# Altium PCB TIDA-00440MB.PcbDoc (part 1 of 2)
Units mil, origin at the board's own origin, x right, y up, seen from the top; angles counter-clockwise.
Board outline 4900 x 4330.71 mil, 4 copper layers (Top Layer, MidLayer1 (GND), MidLayer2 (PWR), Bottom Layer), stack 90 mil thick; 170 components, 89 nets, 419 pads, 132 vias.
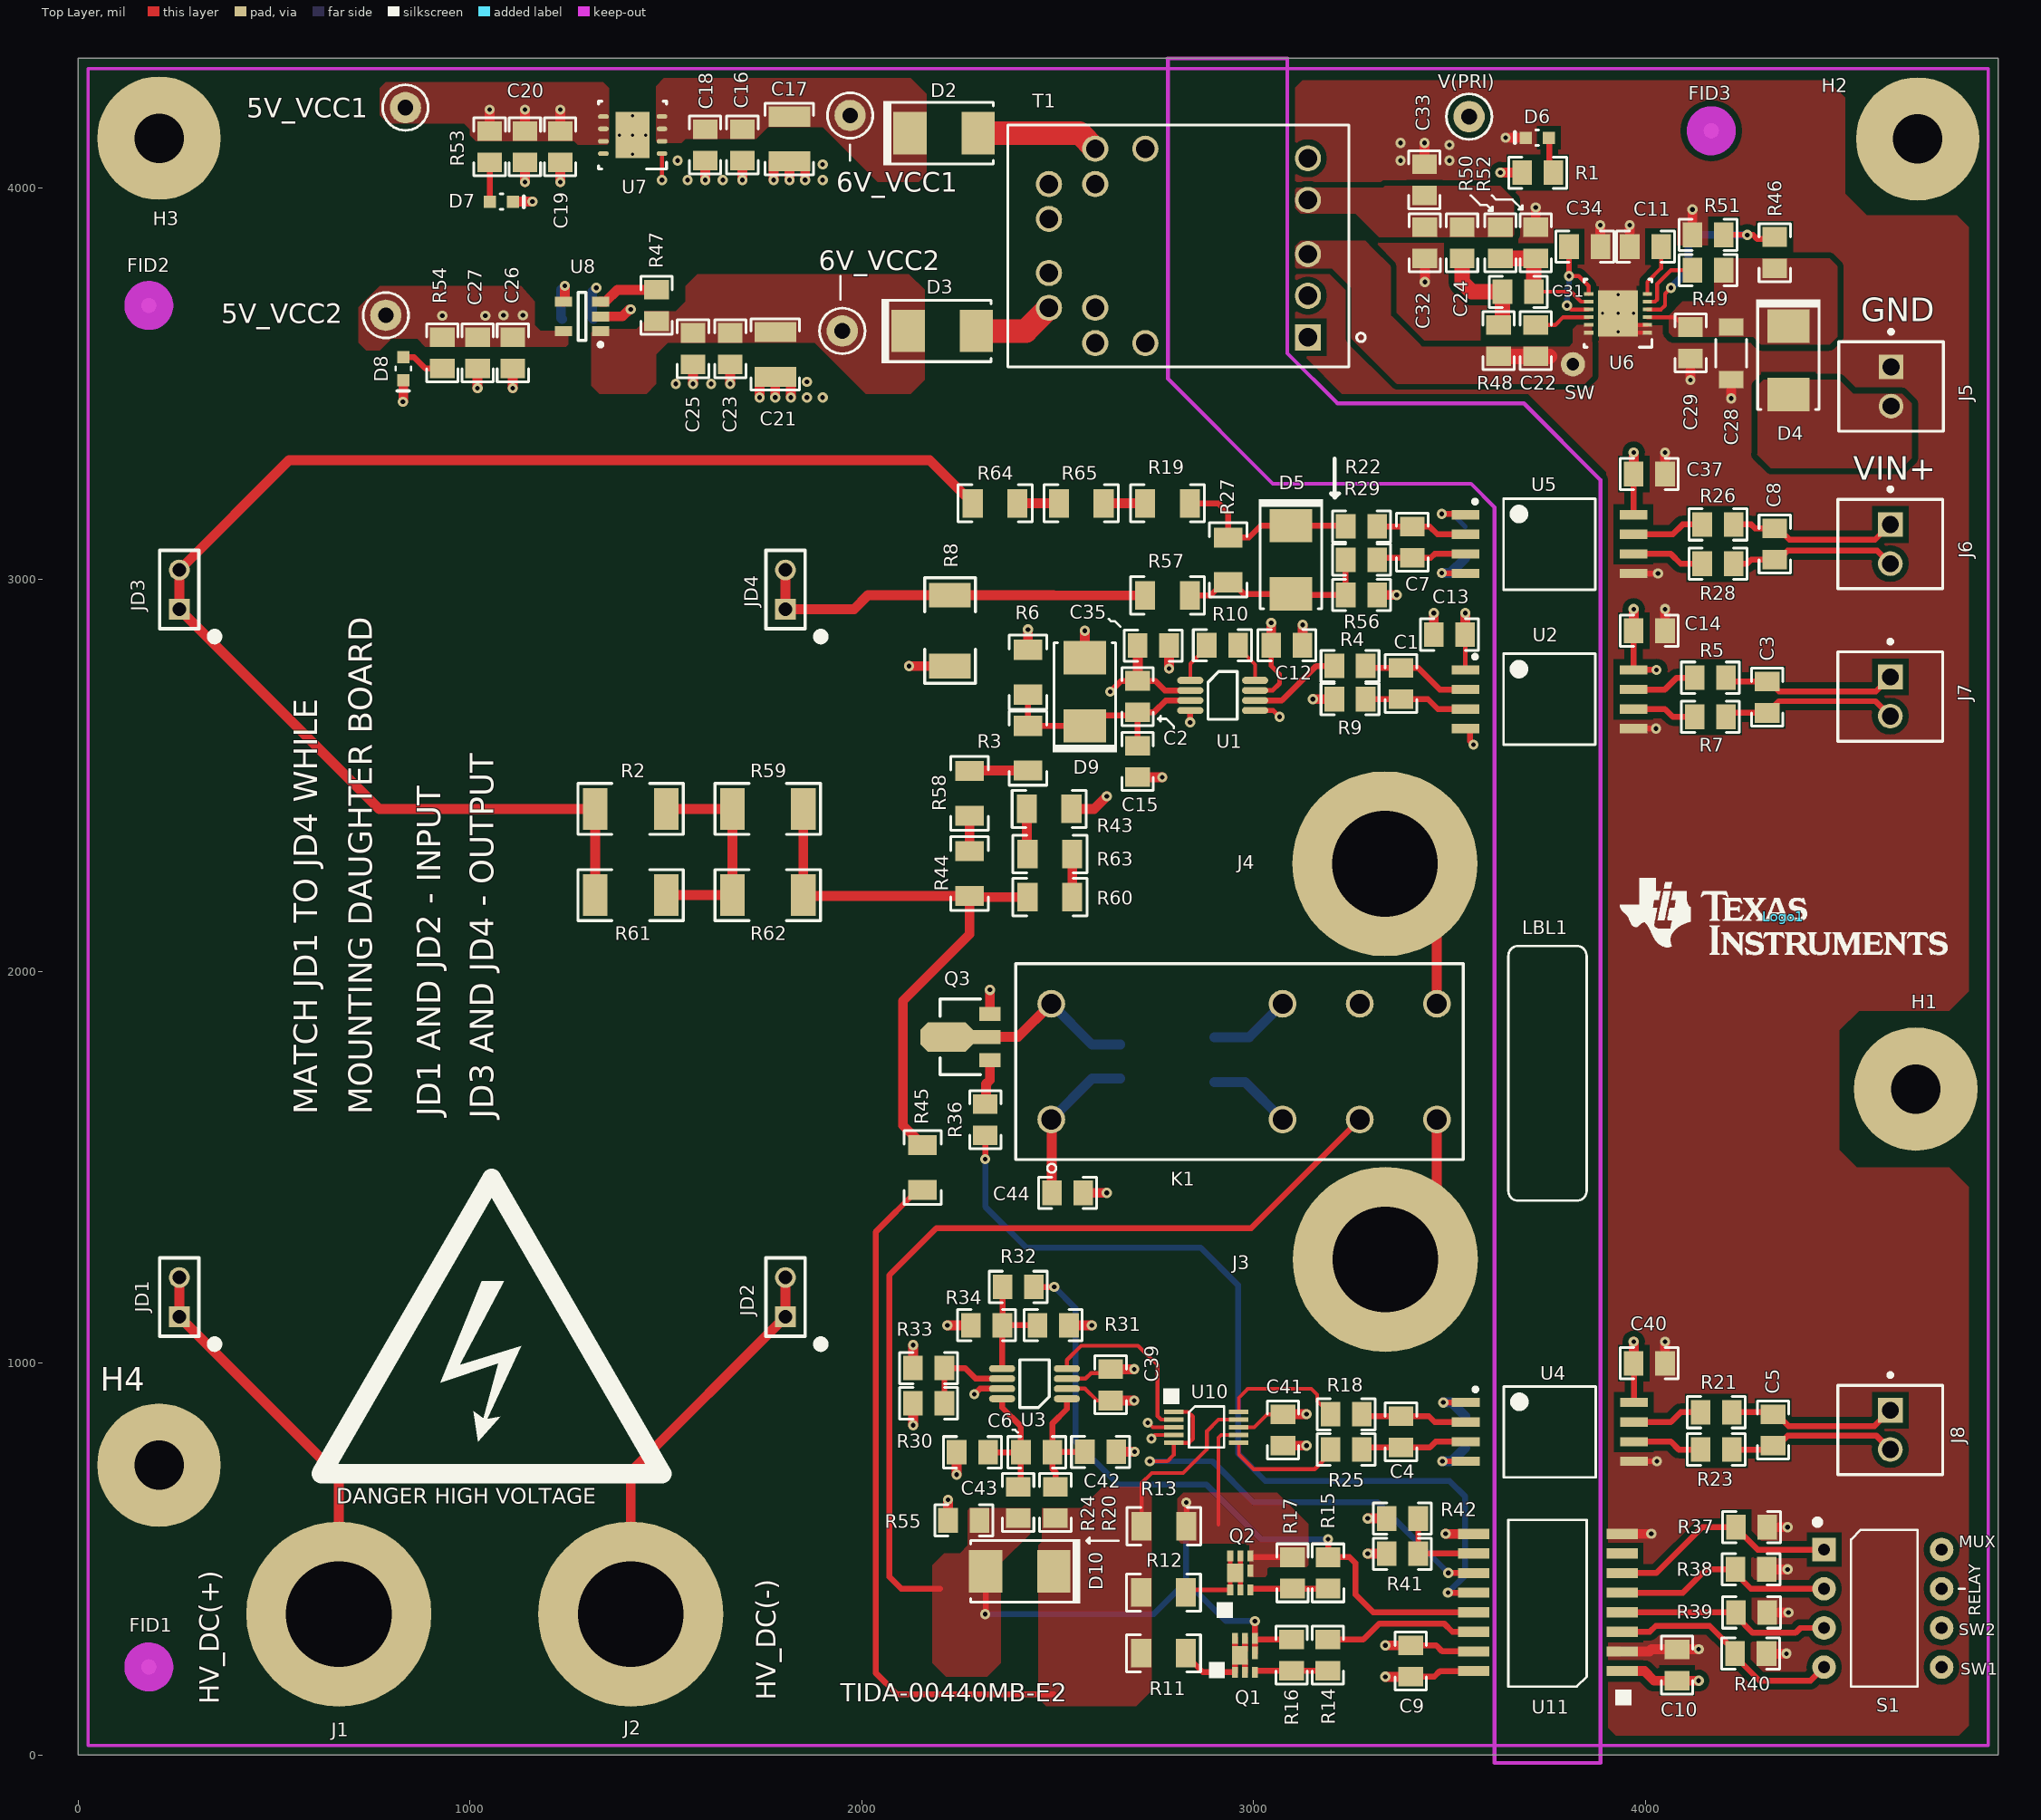
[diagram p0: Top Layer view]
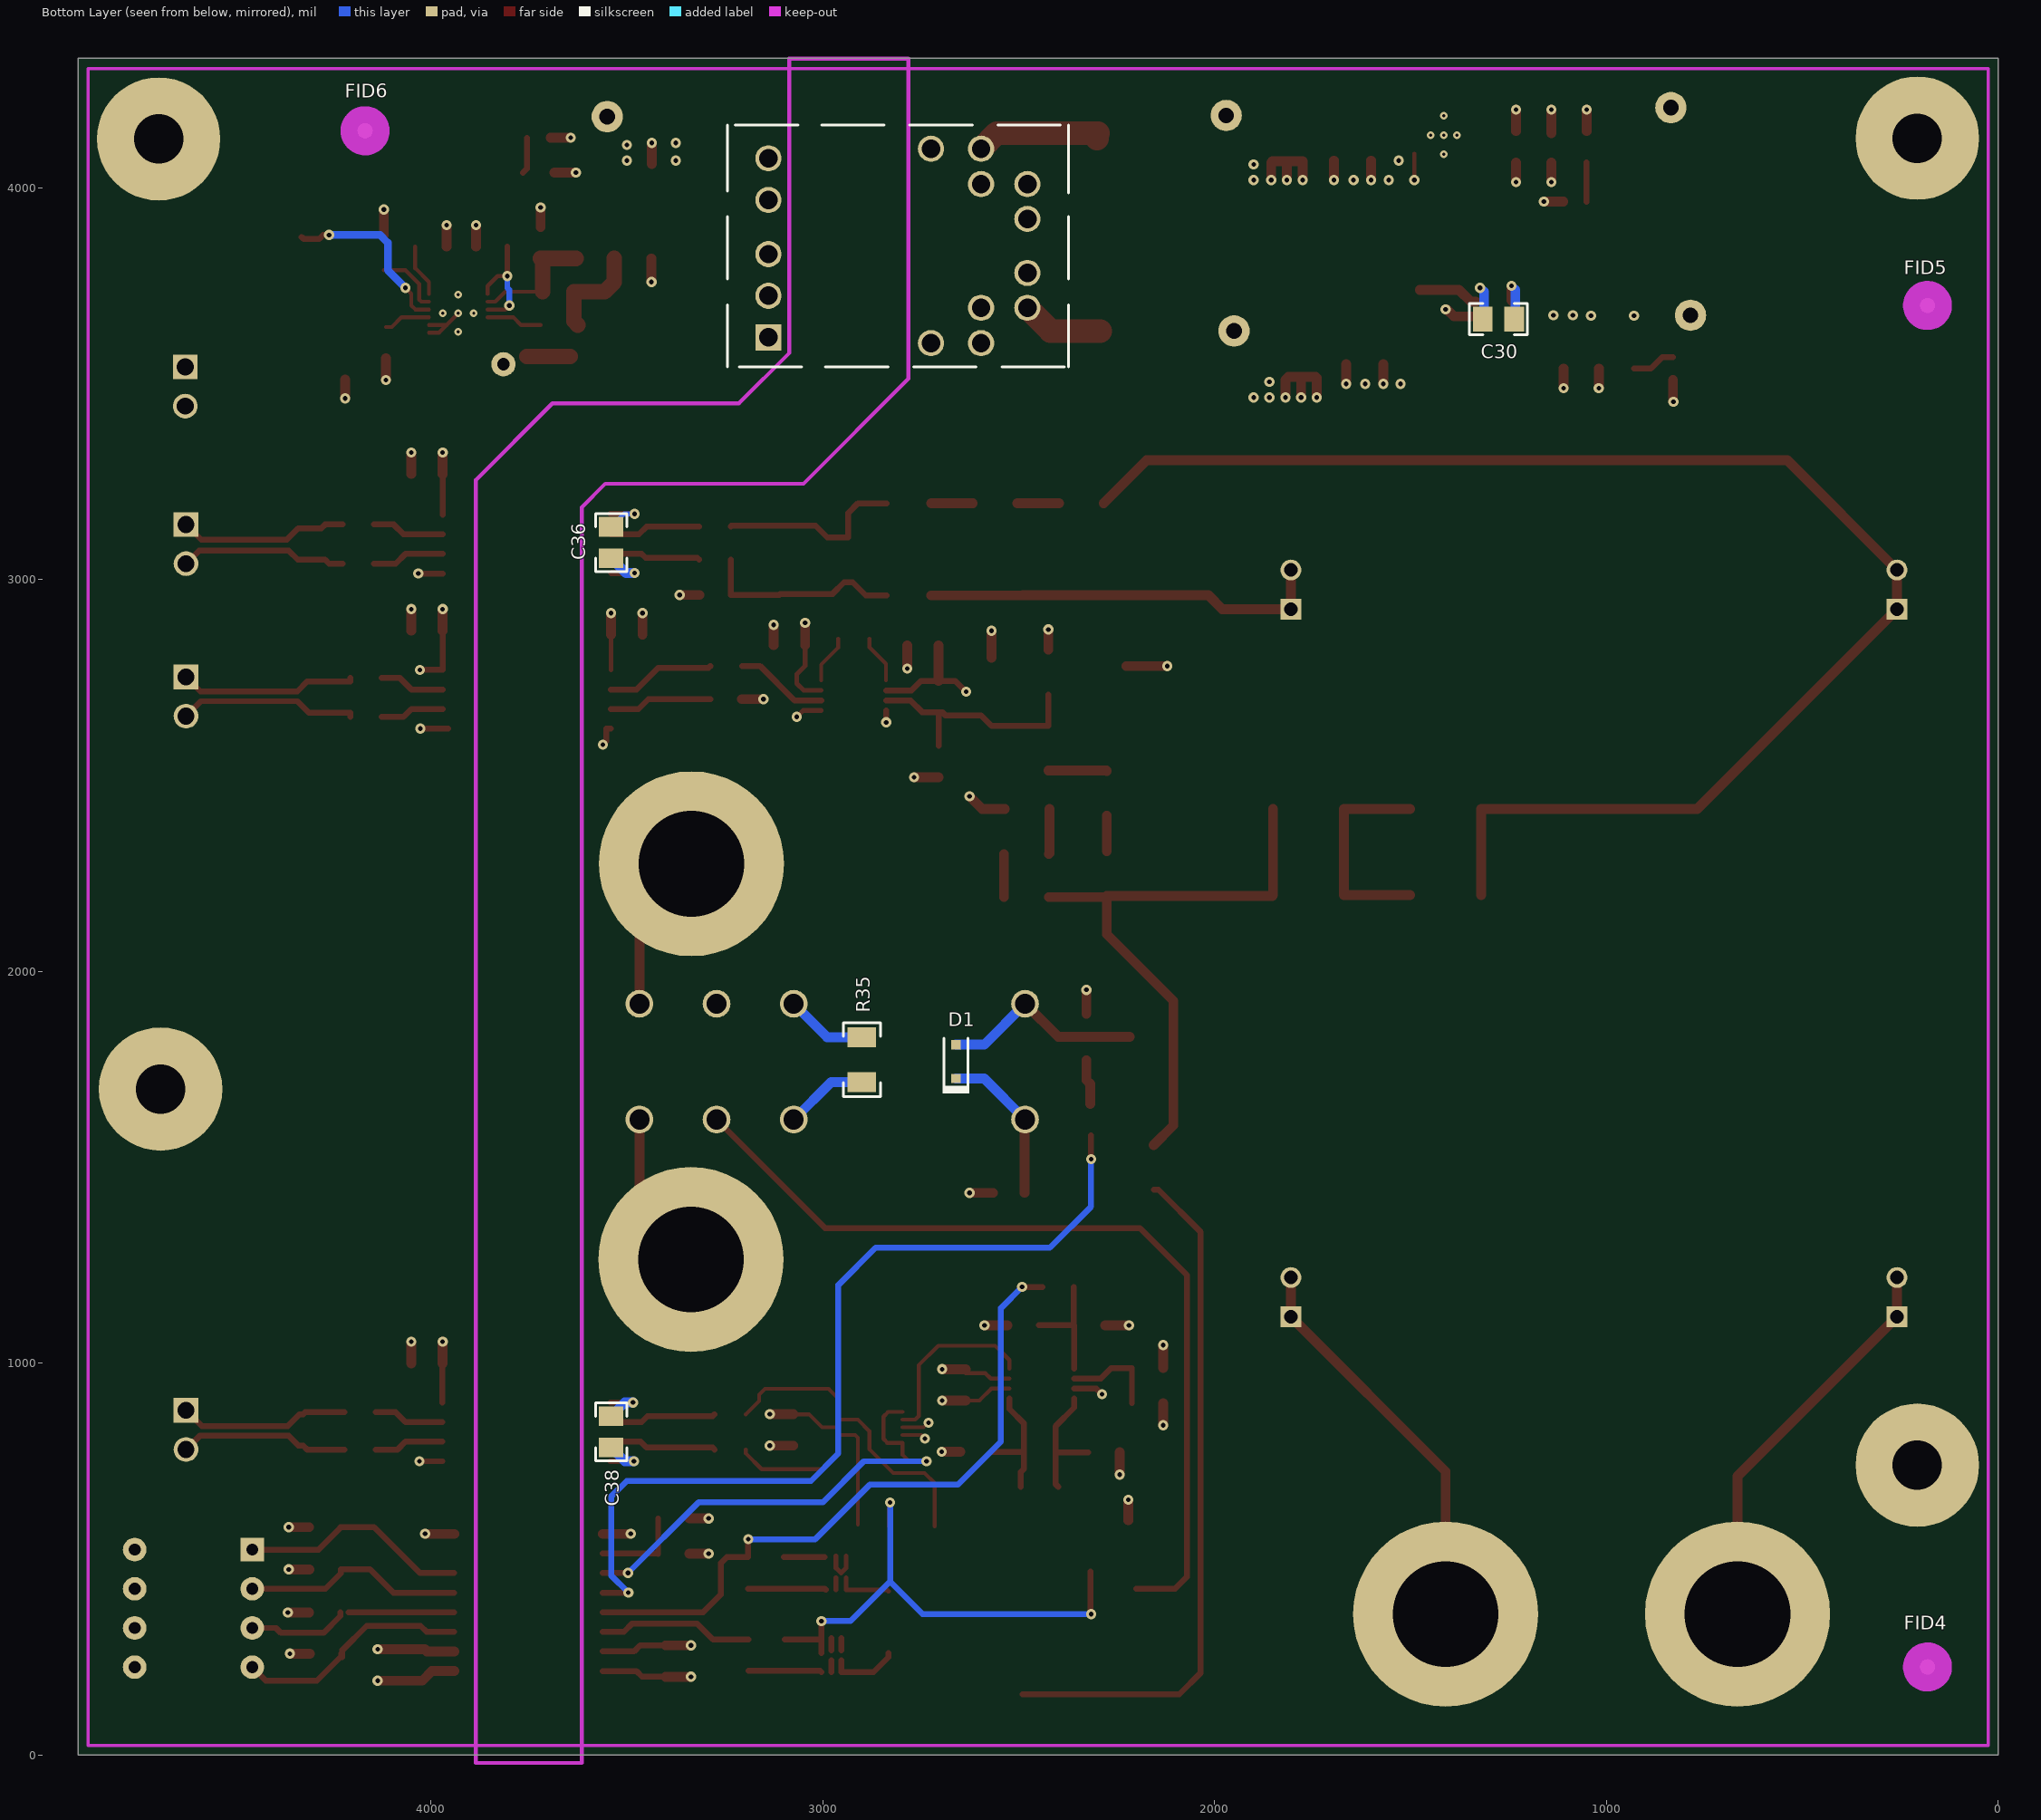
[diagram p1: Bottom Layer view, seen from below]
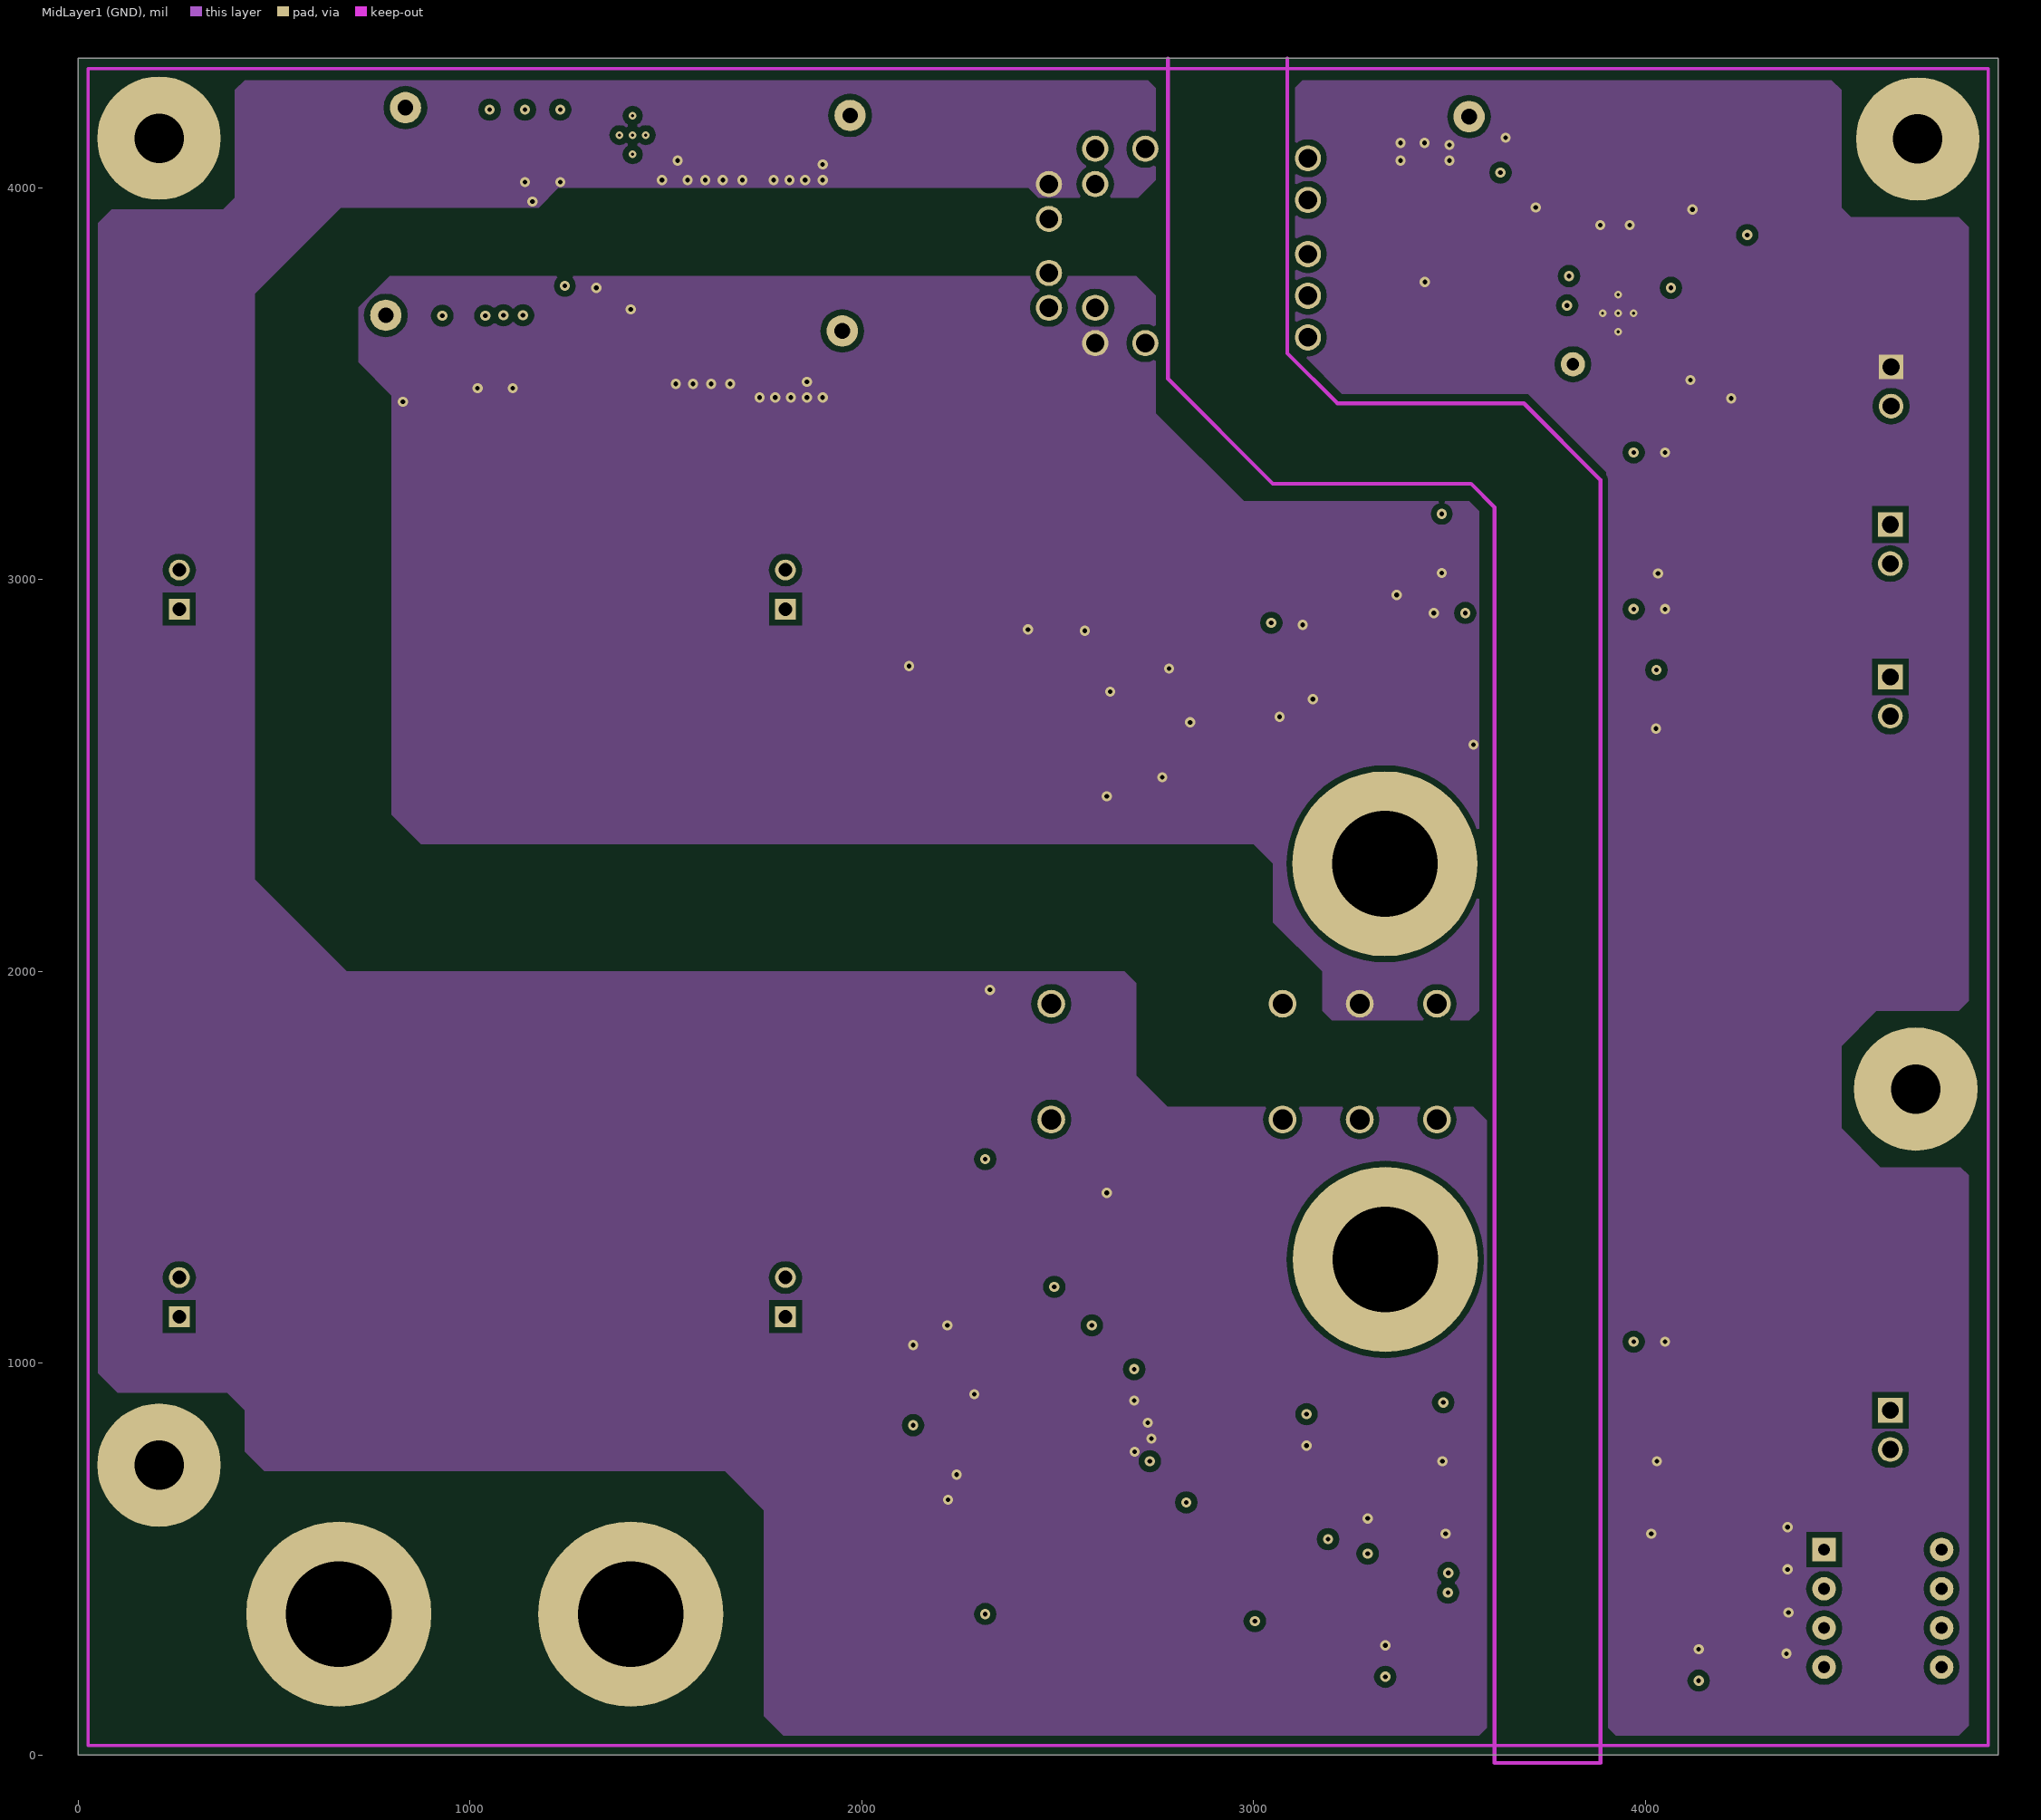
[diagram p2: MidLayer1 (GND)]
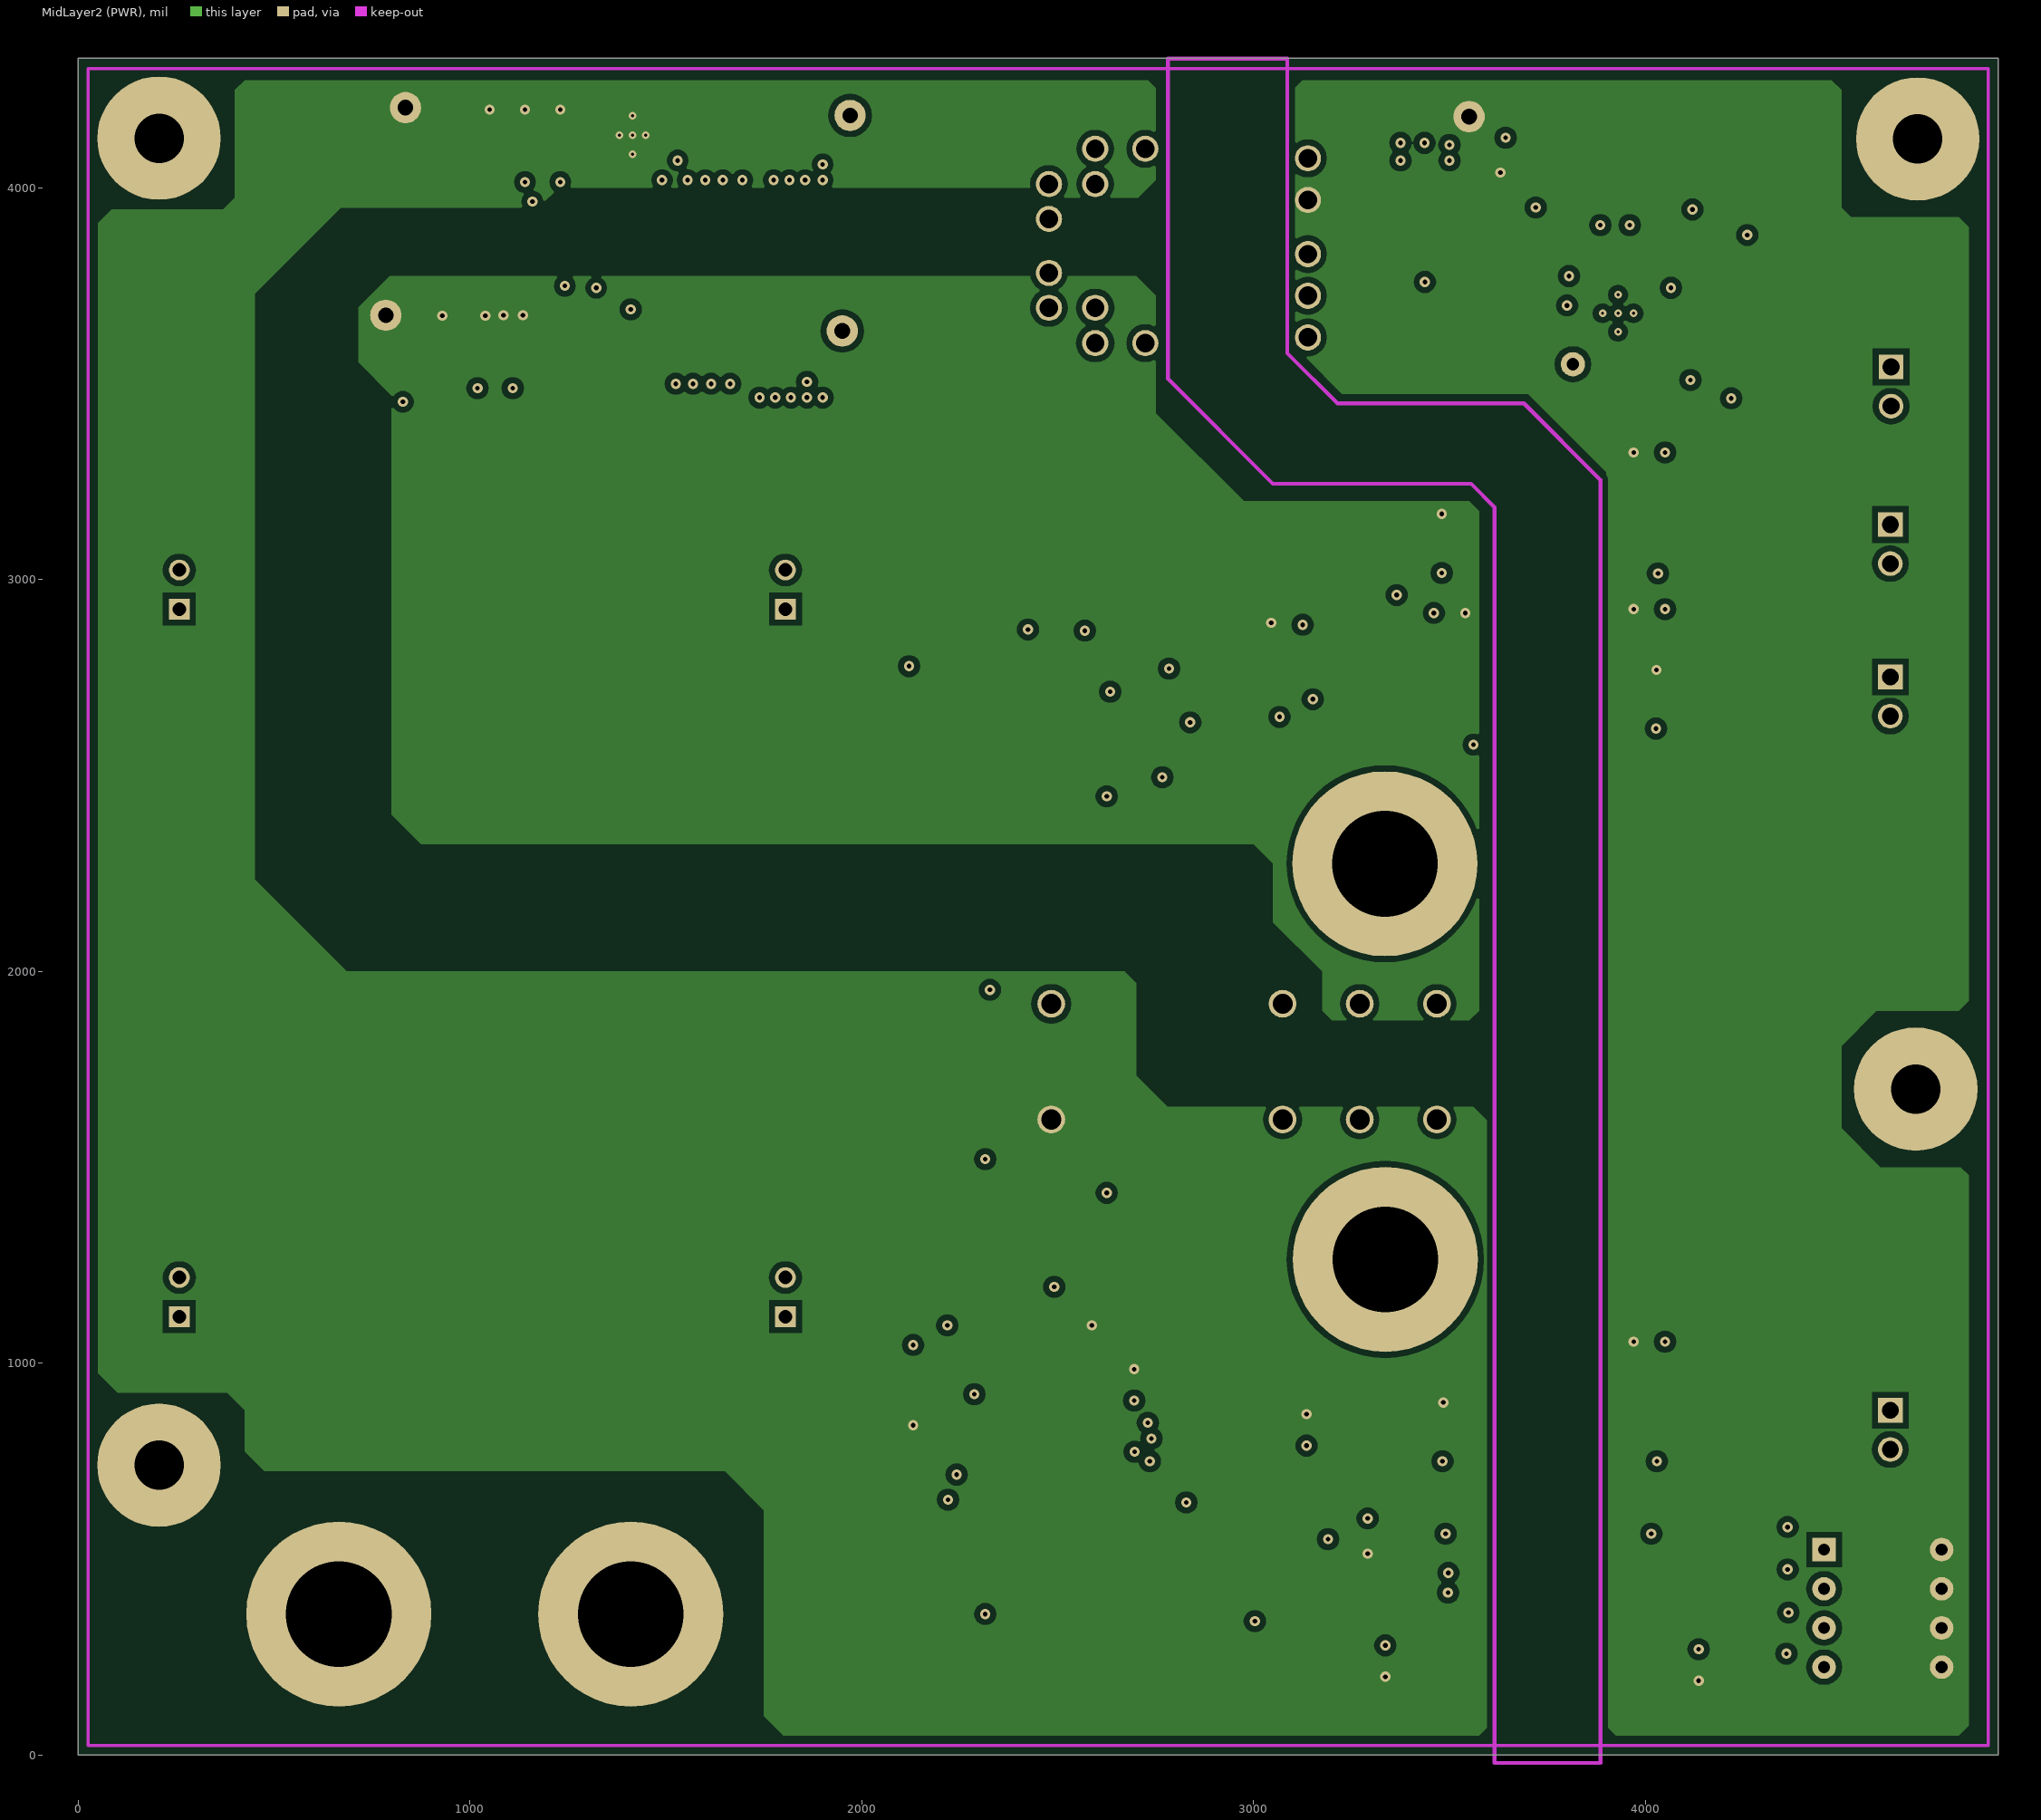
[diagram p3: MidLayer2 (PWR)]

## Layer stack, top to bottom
Top Layer: signal copper 1.4
Dielectric: core 59.2, FR-4, Dk 4.8
MidLayer1 (GND): signal copper 1.4
Dielectric: prepreg 12.6, FR-4, Dk 4.8
MidLayer2 (PWR): signal copper 1.4
Dielectric: core 12.6, FR-4, Dk 4.8
Bottom Layer: signal copper 1.4

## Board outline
0,0 0,4330.71 4900,4330.71 4900,0

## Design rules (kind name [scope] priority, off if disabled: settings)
AcuteAngle [All] p1: minimum=4.50000000000000E+0001 checktracksonly=FALSE
AssemblyTestPointUsage [All] p1: valid=2
Clearance "Poly_ All" [InPolygon] p1: gap=15
Clearance Poly_Poly [InPolygon vs InPolygon] p2: gap=15
Clearance "Less Than 9 mils from PAD to PAD" [(InPadClass('Less than 9 Mil Clearance')) vs (InPadClass('All Pads'))] p3: gap=8
Clearance "SMT Pin Via" [IsVia vs IsSMTPin] p4: gap=8
Clearance "Via to Via" [IsVia vs IsVia] p5: gap=8
Clearance [All] p6: gap=5
ComponentClearance ComponentClearance_Shunt [InComponentClass('Header') vs InComponentClass('Shunt')] p1: gap=0 collisioncheckmode=3 verticalgap=0 showdistances=FALSE
ComponentClearance ComponentClearance_Logo [InComponentClass('Logo')] p2: gap=50 collisioncheckmode=3 verticalgap=10 showdistances=FALSE
ComponentClearance ComponentClearance_ScrewToNut [(HasFootprint('NY PMS 440 0025 PH')) vs (HasFootprint('Keystone_1902C'))] p3: gap=5 collisioncheckmode=3 verticalgap=10 showdistances=FALSE
ComponentClearance ComponentClearance_MountingHoles [InComponentClass('Mounting Holes')] p4: gap=250 collisioncheckmode=3 verticalgap=100000 showdistances=FALSE
ComponentClearance ComponentClearance_SmallPassives [HasFootprint('0201*') or HasFootprint('0402*') or HasFootprint('0508') or HasFootprint('0603*') or HasFootprint('0612') or HasFootprint('0805*') or HasFootprint('0815*') or HasFootprint('0830*') or HasFootprint('1206*') or HasFootprint('1210*') or HasFootprint('1808*') or HasFootprint('1812*') or HasFootprint('1825*') or HasFootprint('2010*') or HasFootprint('2220*') or HasFootprint('2225*') or HasFootprint('2512*') or HasFootprint('2728*') or HasFootprint('3518*') vs HasFootprint('0201*') or HasFootprint('0402*') or HasFootprint('0508') or HasFootprint('0603*') or HasFootprint('0612') or HasFootprint('0805*') or HasFootprint('0815*') or HasFootprint('0830*') or HasFootprint('1206*') or HasFootprint('1210*') or HasFootprint('1808*') or HasFootprint('1812*') or HasFootprint('1825*') or HasFootprint('2010*') or HasFootprint('2220*') or HasFootprint('2225*') or HasFootprint('2512*') or HasFootprint('2728*') or HasFootprint('3518*')] p5: gap=20 collisioncheckmode=3 verticalgap=10 showdistances=FALSE
ComponentClearance ComponentClearance_THtoSMT [IsThruComponent vs IsSMTComponent] p6: gap=50 collisioncheckmode=3 verticalgap=30 showdistances=FALSE
ComponentClearance ComponentClearance_THtoTH [IsThruComponent vs IsThruComponent] p7: gap=118.11 collisioncheckmode=3 verticalgap=30 showdistances=FALSE
ComponentClearance [All] p8: gap=30 collisioncheckmode=3 verticalgap=10 showdistances=FALSE
DiffPairsRouting [All] p1: maxlimit=100 minlimit=10 mostfreqgap=10 maxuncoupledlength=1000
FabricationTestPointUsage TestPointUsage [All] p1: valid=2 allowmultiple=FALSE
FabricationTestpoint Testpoint [All] p1: side=3 testpointundercomponent=TRUE minsize=40 maxsize=100 preferedsize=60 minholesize=0 maxholesize=40 preferedholesize=32 testpointgrid=1 allowsidetop=TRUE allowsidebottom=TRUE usegrid=TRUE gridtolerance=0.01
FanoutControl Fanout_LCC [IsLCC] p1: bgadir=Out bgaviamode=Centered fanoutstyle=Auto fanoutdirection=Alternating viagrid=1 // Fanout_LCC (Default Rule)
FanoutControl Fanout_BGA [IsBGA] p2: bgadir=Out bgaviamode=Centered fanoutstyle=Auto fanoutdirection=Alternating viagrid=1 // Fanout_BGA (Default Rule)
FanoutControl Fanout_Default [All] p4: bgadir=Out bgaviamode=Centered fanoutstyle=Auto fanoutdirection=Alternating viagrid=1 // Fanout_Default (Default Rule)
FanoutControl Fanout_Small [(CompPinCount < 5)] p5: bgadir=Out bgaviamode=Centered fanoutstyle=Auto fanoutdirection=OutThenIn viagrid=1 // Fanout_Small (Default Rule)
HoleSize [All] p1: absolutevalues=TRUE maxlimit=300 minlimit=7 maxpercent=80.000 minpercent=20.000
MinimumAnnularRing MinimumAnnularRing_ThermalPadVias [IsVia and InAnyComponent] p1: minimumring=5.91
MinimumAnnularRing [All] p2: minimumring=5.91
MinimumSolderMaskSliver MinimumSolderMaskSliver_Logo [InComponentClass('Logo') vs InComponentClass('Logo')] p1: minsoldermaskwidth=0.7
MinimumSolderMaskSliver [All] p2: minsoldermaskwidth=3.94
PlaneConnect [All] p1: planeconnectstyle=Relief reliefexpansion=10 reliefentries=4 reliefconductorwidth=10 reliefairgap=10
PolygonConnect [All] p1: connectstyle=Direct reliefconductorwidth=10 reliefentries=4 polygonreliefangle="90 Angle" airgapwidth=10
RoutingVias [All] p1: holewidth=12 width=26 viastyle="Through Hole" minholewidth=12 minwidth=26 maxholewidth=20 maxwidth=40
SMDToCorner [All] p1: distance=30000
SilkToSilkClearance [All] p1: silktosilkclearance=0
SilkscreenOverComponentPads [All] p1: minsilkscreentomaskgap=5
SolderMaskExpansion [All] p1: expansion=2.5
Width PWR [InNetClass('PWR and GND')] p1: maxlimit=40 minlimit=10 preferedwidth=25 checkconnectedcopper=TRUE
Width [All] p2: maxlimit=100 minlimit=10 preferedwidth=15
14 further rules are at their usual default settings.

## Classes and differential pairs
component class FiducialMark: FID1 FID2 FID3 FID4 FID5 FID6
pad class "New Class": U7-9
component class "Mounting Holes": H1 H2 H3 H4
component class Logo: Logo1
pad class "Less than 9 Mil Clearance": U2-6 U2-7 U2-8
component class Pg2-Main: C1 C2 C3 C4 C5 C6 C7 C8 C9 C10 C12 C13 C14 C15 C35 C36 C37 C38 C39 C40 C41 C42 C43 C44 D1 D5 D9 D10 J1 J2 J3 J4 J6 J7 J8 JD1 JD2 JD3 JD4 K1 Q1 Q2 Q3 R2 R3 R4 R5 R6 R7 R8 R9 R10 R11 R12 R13 R14 R15 R16 R17 R18 R19 R20 R21 R22 R23 R24 R25 R26 R27 R28 R29 R30 R31 R32 R33 R34 R35 R36 R37 R38 R39 R40 R41 R42 R43 R44 R45 R55 R56 R57 R58 R59 R60 R61 R62 R63 R64 R65 S1 U1 U2 U3 U4 U5 U10 U11
component class AssemblyNote: ZZ1 ZZ2 ZZ3 ZZ4
component class Pg4_Hardware_ANSI-B: !PCB "DANGER HIGH VOLTAGE" FID1 FID2 FID3 FID4 FID5 FID6 H1 H2 H3 H4 LBL1 Logo1 ZZ1 ZZ2 ZZ3 ZZ4
component class Pg3: 5V_VCC1 5V_VCC2 6V_VCC1 6V_VCC2 C11 C16 C17 C18 C19 C20 C21 C22 C23 C24 C25 C26 C27 C28 C29 C30 C31 C32 C33 C34 D2 D3 D4 D6 D7 D8 J5 R1 R46 R47 R48 R49 R50 R51 R52 R53 R54 SW T1 U6 U7 U8 V(PRI)
component class Label: LBL1

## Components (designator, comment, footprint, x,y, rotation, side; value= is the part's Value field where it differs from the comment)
5V_VCC1 "5000" Keystone5000 835,4205 r180 top
5V_VCC2 "5000" Keystone5000 785,3675 r180 top
6V_VCC1 "5000" Keystone5000 1970,4185 r90 top
6V_VCC2 "5000" Keystone5000 1950,3635 r90 top
C1 "0805ZD105KAT2A" 0805_HV 3376,2735 r270 top
C2 "08055A101JAT2A" 0805_HV 2704,2702 r90 top
C3 "GRM216R71E102KA01D" 0805_HV 4311,2700 r270 top
C4 "0805ZD105KAT2A" 0805_HV 3376,825 r270 top
C5 "GRM216R71E102KA01D" 0805_HV 4326,830 r270 top
C6 "0805ZD105KAT2A" 0805_HV 2446,773 r180 top
C7 "0805ZD105KAT2A" 0805_HV 3405,3096 r270 top
C8 "GRM216R71E102KA01D" 0805_HV 4330,3091 r270 top
C9 "CC0805KRX7R7BB104" 0805_HV 3401,240 r90 top
C10 "CC0805KRX7R7BB104" 0805_HV 4081,230 r90 top
C11 "C2012C0G1E103J" 0805_HV 4000,3850 r180 top
C12 "CC0805KRX7R7BB104" 0805_HV 3085,2833 r0 top
C13 "CC0805KRX7R7BB104" 0805_HV 3500,2860 r180 top
C14 "CC0805KRX7R7BB104" 0805_HV 4010,2870 r0 top
C15 "C2012C0G1E103J" 0805_HV 2704,2536 r90 top
C16 "GRM21BR71A105KA01L" 0805_HV 1695,4110 r270 top
C17 "GRM32DR71A106KA01L" 1210 1815,4125 r270 top
C18 "CC0805KRX7R7BB104" 0805_HV 1600,4110 r270 top
C19 "CC0805KRX7R7BB104" 0805_HV 1230,4105 r270 top
C20 "GRM21BR71A105KA01L" 0805_HV 1140,4105 r270 top
C21 "GRM32DR71A106KA01L" 1210 1779,3575 r90 top
C22 "C2012C0G1E103J" 0805_HV 3720,3610 r270 top
C23 "GRM21BR71A105KA01L" 0805_HV 1664,3590 r270 top
C24 "C2012C0G1E103J" 0805_HV 3532,3860 r270 top
C25 "CC0805KRX7R7BB104" 0805_HV 1569,3590 r270 top
C26 "CC0805KRX7R7BB104" 0805_HV 1109,3579 r270 top
C27 "GRM21BR71A105KA01L" 0805_HV 1019,3579 r90 top
C28 "GMK316BJ106KL-T" 1206_190 4219,3578 r270 top
C29 "08053C104KAT2A" 0805_HV 4115,3605 r270 top
C30 "GRM216R71E102KA01D" 0805_HV 1275,3665 r0 bottom
C31 "GRM216R71E102KA01D" 0805_HV 3675,3735 r180 top
C32 "C2012JB1V226M125AC" 0805_HV 3437,3860 r270 top
C33 "C2012JB1V226M125AC" 0805_HV 3436,4021 r90 top
C34 "GMK212B7105KG-T" 0805_HV 3845,3850 r0 top
C35 "C2012C0G1E103J" 0805_HV 2744,2832 r0 top
C36 "CC0805KRX7R7BB104" 0805_HV 3540,3095 r270 bottom
C37 "CC0805KRX7R7BB104" 0805_HV 4010,3270 r0 top
C38 "CC0805KRX7R7BB104" 0805_HV 3540,825 r270 bottom
C39 "CC0805KRX7R7BB104" 0805_HV 2635,945 r270 top
C40 "CC0805KRX7R7BB104" 0805_HV 4010,1000 r0 top
C41 "CC0805KRX7R7BB104" 0805_HV 3075,830 r270 top
C42 "C2012C0G1E103J" 0805_HV 2609,774 r180 top
C43 "C2012C0G1E103J" 0805_HV 2282,773 r180 top
C44 "CC0805KRX7R7BB104" 0805_HV 2525,1435 r0 top
D1 "1SS315TPH3F" sod-323 2660,1770 r90 bottom
D2 "10BQ040TRPBF" SMB 2210,4140 r0 top
D3 "10BQ040TRPBF" SMB 2205,3635 r0 top
D4 "10BQ040TRPBF" SMB 4365,3560 r270 top
D5 "SMBJ5.0A-13-F" SMB 3095,3051 r270 top
D6 "LG L29K-G2J1-24-Z" "LG L29K_GREEN" 3724,4128 r180 top
D7 "LG L29K-G2J1-24-Z" "LG L29K_GREEN" 1080,3965 r0 top
D8 "LG L29K-G2J1-24-Z" "LG L29K_GREEN" 829.69,3538.94 r270 top
D9 "SMBJ5.0A-13-F" SMB 2569,2714 r90 top
D10 "SMBJ5.0A-13-F" SMB 2403,469 r180 top
"DANGER HIGH VOLTAGE" "DANGER HIGH VOLTAGE" IEC_HighVoltage_Large 1055,1070 r0 top
FID1 "Fiducial" Fiducial10-30 180,225 r0 top
FID2 "Fiducial" Fiducial10-30 180,3700 r90 top
FID3 "Fiducial" Fiducial10-30 4168,4146 r90 top
FID4 "Fiducial" Fiducial10-30 180,225 r90 bottom
FID5 "Fiducial" Fiducial10-30 180,3700 r90 bottom
FID6 "Fiducial" Fiducial10-30 4168,4146 r90 bottom
H1 "NY PMS 440 0025 PH" "NY PMS 440 0025 PH" 4690,1700 r0 top
H2 "NY PMS 440 0025 PH" "NY PMS 440 0025 PH" 4695,4125 r0 top
H3 "NY PMS 440 0025 PH" "NY PMS 440 0025 PH" 206,4127 r0 top
H4 "NY PMS 440 0025 PH" "NY PMS 440 0025 PH" 206,740 r0 top
J1 "3267" Pomona_3267 665,360 r90 top
J2 "3267" Pomona_3267 1410,360 r90 top
J3 "3267" Pomona_3267 3336,1265 r180 top
J4 "3267" Pomona_3267 3335,2275 r180 top
J5 "282834-2" TEC_282834-2 4627,3493 r270 top
J6 "282834-2" TEC_282834-2 4625,3091 r270 top
J7 "282834-2" TEC_282834-2 4625,2702 r270 top
J8 "282834-2" TEC_282834-2 4625,830 r270 top
JD1 "5-534206-1" CONN_534206-1 257.76,1169 r90 top
JD2 "5-534206-1" CONN_534206-1 1805,1169 r90 top
JD3 "5-534206-1" CONN_534206-1 257.76,2974.9 r90 top
JD4 "5-534206-1" CONN_534206-1 1805,2974.9 r90 top
K1 "G2RL-2 DC5" RELAY_G2RL-2_24 2946,1770 r0 top
LBL1 "Size: 0.65\" x 0.20 \"" Label_650x200 3750,1740 r90 top
Logo1 "Texas Instruments" TI_Stacked_Overlay_Small 4353,2140 r0 top
Q1 "TR-CSD13202Q2" SON_2X2MM 2977.8,255 r0 top
Q2 "TR-CSD13202Q2" SON_2X2MM 2966,465 r0 top
Q3 "2DD1664R-13" SOT-89-3 2252,1833 r180 top
R1 "CRCW08051K00FKEA" 0805_HV 3725,4039 r0 top
R2 "CRCW2010499KFKEF" 2010 1410,2415 r0 top
R3 "CRCW12067M50FKEA" 1206 2424,2570 r270 top
R4 "RT0805BRD0710RL" 0805_HV 3246,2780 r0 top
R5 "CRCW0805470RFKEA" 0805_HV 4166,2750 r0 top
R6 "CRCW12066K80JNEA" 1206 2424,2764 r270 top
R7 "CRCW0805470RFKEA" 0805_HV 4166,2650 r0 top
R8 "CRCW20100000Z0EF" 2010 2225,2870 r270 top
R9 "RT0805BRD0710RL" 0805_HV 3246,2695 r0 top
R10 "CRCW080551K0JNEA" 0805_HV 2920,2833 r0 top
R11 "RC1206FR-07261RL" 1206 2770,260 r180 top
R12 "RC1206FR-072K7L" 1206 2770,415 r180 top
R13 "RC1206FR-07220KL" 1206 2771,584 r180 top
R14 "CRCW08052K00FKEA" 0805_HV 3189.11,255 r270 top
R15 "CRCW08052K00FKEA" 0805_HV 3190,465 r270 top
R16 "CRCW080510K0FKEA" 0805_HV 3097.11,255 r270 top
R17 "CRCW080510K0FKEA" 0805_HV 3099,465 r270 top
R18 "RT0805BRD0710RL" 0805_HV 3236,870 r0 top
R19 "CRCW12063M00JNEA" 1206 2780,3195 r180 top
R20 "RT0805BRD0710RL" 0805_HV 2494,645 r90 top
R21 "CRCW0805470RFKEA" 0805_HV 4181,875 r0 top
R22 "RT0805BRD0710RL" 0805_HV 3275,3136 r0 top
R23 "CRCW0805470RFKEA" 0805_HV 4181,780 r0 top
R24 "RT0805BRD0710RL" 0805_HV 2399,645 r90 top
R25 "RT0805BRD0710RL" 0805_HV 3236,780 r0 top
R26 "CRCW0805470RFKEA" 0805_HV 4185,3141 r0 top
R27 "CRCW12063K00JNEA" 1206 2935,3050.69 r90 top
R28 "CRCW0805470RFKEA" 0805_HV 4185,3041 r0 top
R29 "RT0805BRD0710RL" 0805_HV 3275,3051 r0 top
R30 "ERJ-6GEY0R00V" 0805_HV 2170.69,898 r0 top
R31 "ERJ-6GEY0R00V" 0805_HV 2488.69,1097 r180 top
R32 "ERJ-6GEY0R00V" 0805_HV 2399,1195 r180 top
R33 "ERJ-6GEY0R00V" 0805_HV 2170.69,988 r0 top
R34 "ERJ-6GEY0R00V" 0805_HV 2318.69,1097 r0 top
R35 "CRCW120610M0JNEA" 1206 2900,1775 r270 bottom
R36 "ERJ-6GEY0R00V" 0805_HV 2315,1622 r270 top
R37 "ERJ-6GEY0R00V" 0805_HV 4271,582 r0 top
R38 "ERJ-6GEY0R00V" 0805_HV 4270,474 r0 top
R39 "ERJ-6GEY0R00V" 0805_HV 4271,364 r0 top
R40 "ERJ-6GEY0R00V" 0805_HV 4269,259 r0 top
R41 "ERJ-6GEY0R00V" 0805_HV 3380,514 r0 top
R42 "ERJ-6GEY0R00V" 0805_HV 3380,604 r0 top
R43 "CRCW12067M50FKEA" 1206 2478,2415 r180 top
R44 "CRCW12067M50FKEA" 1206 2275,2250 r270 top
R45 "CRCW12060000Z0EA" 1206 2155,1500 r90 top
R46 "RT0805BRD07126KL" 0805_HV 4330,3835 r270 top
R47 "ERJ-6GEY0R00V" 0805_HV 1476,3700 r270 top
R48 "RT0805BRD0735K2L" 0805_HV 3625,3610 r90 top
R49 "RT0805BRD07145KL" 0805_HV 4160,3790 r180 top
R50 "CRCW080512K7FKEA" 0805_HV 3630,3860 r90 top
R51 "CRCW080519K6FKEA" 0805_HV 4160,3880 r0 top
R52 "CRCW080520K0FKEA" 0805_HV 3720,3860 r270 top
R53 "CRCW08051K00FKEA" 0805_HV 1050,4105 r270 top
R54 "CRCW08051K00FKEA" 0805_HV 929,3579 r270 top
R55 "CRCW08050000Z0EA" 0805_HV 2260,599 r0 top
R56 "CRCW08050000Z0EA" 0805_HV 3275,2961 r180 top
R57 "CRCW12060000Z0EA" 1206 2780,2960 r0 top
R58 "CRCW12067M50FKEA" 1206 2275,2455 r270 top
R59 "CRCW2010499KFKEF" 2010 1760,2415 r0 top
R60 "CRCW12067M50FKEA" 1206 2480,2190 r180 top
R61 "CRCW2010499KFKEF" 2010 1410,2195 r0 top
R62 "CRCW2010499KFKEF" 2010 1760,2195 r0 top
R63 "CRCW12067M50FKEA" 1206 2480,2300 r0 top
R64 "CRCW12063M00JNEA" 1206 2340,3195 r180 top
R65 "CRCW12063M00JNEA" 1206 2560,3195 r180 top
S1 "78B04ST" SW_78B04ST 4606,374.53 r0 top
SW "TP-032_RND" TP-032_RND 3815,3550 r0 top
T1 "750342773" WURTH_750342773 2808,3852 r180 top
U1 "INA333AIDGK" DGK0008A_N 2921,2704.69 r0 top
U2 "AMC1200BDWV" DWV0008A 3755,2695 r0 top
U3 "INA225AIDGK" DGK0008A_N 2440.69,948 r180 top
U4 "AMC1200BDWV" DWV0008A 3756,825 r0 top
U5 "AMC1200BDWV" DWV0008A 3755,3091 r0 top
U6 "LM5160ADNTR" DNT0012B 3930,3680 r180 top
U7 "TLV1117-50IDRJR" DRJ0008A 1415,4135 r180 top
U8 "LP2985AIM5-5.0" MF05A_N 1285.68,3672 r180 top
U10 "TS5A23157DGS" DGS_10P 2878,837 r0 top
U11 "ISO7640FM" DW16 3751,389.53 r180 top
V(PRI) "5000" Keystone5000 3550,4182 r0 top
ZZ1 "This Assembly Note is for PCB labels only" AssemblyNoteLabel 180,4810 r0 top
ZZ2 "These assemblies are ESD sensitive, ESD precautions shall be observed." AssemblyNote 180,4740 r0 top
ZZ3 "These assemblies must be clean and free from flux and all contaminants. Use of no clean flux is not acceptable." AssemblyNote 180,4670 r0 top
ZZ4 "These assemblies must comply with workmanship standards IPC-A-610 Class 2, unless otherwise specified." AssemblyNote 180,4600 r0 top

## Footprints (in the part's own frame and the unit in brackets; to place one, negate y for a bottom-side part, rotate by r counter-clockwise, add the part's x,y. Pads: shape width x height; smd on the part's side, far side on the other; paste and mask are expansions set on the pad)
0805_HV [mil] "0805 with 30mil clearance between pads"
  rect 50x63 smd: 1(-40,0) 2(40,0)
  silkscreen extent -74,-40 74,40, body extent -43,-29 43,29, height 43
1206 [mm] "1206 from SM-752 data"
  rect 1.3x1.85 smd: 1(-1.45,0) 2(1.45,0)
  silkscreen extent -2.4,-1.21 2.4,1.21, body extent -1.7,-0.9 1.7,0.9, height 1.35
1206_190 [mm] "1206_190"
  rect 1.1x1.6 smd: 1(-1.7,0) 2(1.7,0)
  silkscreen extent -0.9,-1 0.9,1, body extent -1.75,-0.95 1.75,0.95, height 1.9
1210 [mm] "1210 from SM-752 data"
  rect 1.3x2.7 smd: 1(-1.45,0) 2(1.45,0)
  silkscreen extent -2.32,-1.57 2.32,1.57, body extent -1.7,-1.35 1.7,1.35, height 1.35
2010 [mm] "Chip Capacitor, Body 5.08x2.54mm, IPC Medium Density"
  rect 1.6x2.7 smd: 1(-2.3,0) 2(2.3,0)
  silkscreen extent -3.42,-1.65 3.42,1.65, body extent -2.73,-1.45 2.73,1.45, height 1.66
AssemblyNote [mil] "Assembly Note"
AssemblyNoteLabel [mil] "Assembly Note for PCB Labels"
CONN_534206-1 [mm] "TE_CONNECTIVITY"
  rect 1.35x1.35 hole 0.89: 1(-1.27,0)
  round 1.35 hole 0.89: 2(1.27,0)
  silkscreen extent -3.3,-2.54 2.54,1.27, body extent -2.51,-1.27 2.51,1.27, height 8.65
DGK0008A_N [mm] "TSOP, 8-Leads, Body 3x3mm, Pitch 0.65mm, IPC Medium Density"
  oval 1.7x0.45 smd mask+0.05: 1(-2.1,0.975) 2(-2.1,0.325) 3(-2.1,-0.325) 4(-2.1,-0.975) 5(2.1,-0.975) 6(2.1,-0.325) 7(2.1,0.325) 8(2.1,0.975)
  silkscreen extent -0.95,-1.55 0.95,1.55, body extent -2.45,-1.5 2.45,1.5, height 0.94
DGS_10P [mil]
  rect 50x11 smd: 1(-82,39) 2(-82,19.3) 3(-82,-0.4) 4(-82,-20.1) 5(-82,-39.8) 6(84,-39.8) 7(84,-20.1) 8(84,-0.4) 9(84,19.3) 10(84,39)
  silkscreen extent -108,59 -68,99
DNT0012B [mm] "SON, 12-Leads, Body 4x4mm, Pitch 0.5mm"
  rect 0.6x0.25 smd: 1(-1.9,1.25) 2(-1.9,0.75) 3(-1.9,0.25) 4(-1.9,-0.25) 5(-1.9,-0.75) 6(-1.9,-1.25) 7(1.9,-1.25) 8(1.9,-0.75) 9(1.9,-0.25) 10(1.9,0.25) 11(1.9,0.75) 12(1.9,1.25)
  rect 2.6x3 smd paste-1.3: 13(0,0)
  silkscreen extent -2.2,-2.2 2.2,2.2, body extent -2.05,-2.05 2.05,2.05, height 0.81
DRJ0008A [mm] "SON, 8-Leads, Body 4x4mm, Pitch 0.8mm, Thermal Pad 3x2.2mm, TI Recommended"
  oval 0.7x0.3 smd: 1(-1.9,1.2) 2(-1.9,0.4) 3(-1.9,-0.4) 4(-1.9,-1.2) 5(1.9,-1.2) 6(1.9,-0.4) 7(1.9,0.4) 8(1.9,1.2)
  rect 2.2x3 smd paste-1.1: 9(0,0)
  silkscreen extent -2.2,-2.2 2.2,2.2, body extent -2.05,-2.05 2.05,2.05, height 0.81
DW16 [mil]
  rect 80x26 smd: 1(-189.4,174.9) 2(-189.4,124.9) 3(-189.4,74.9) 4(-189.4,24.9) 5(-189.4,-25.1) 6(-189.4,-75.1) 7(-189.4,-125.1) 8(-189.4,-175.1) 9(189.6,-175.1) 10(189.6,-125.1) 11(189.6,-75.1) 12(189.6,-25.1) 13(189.6,24.9) 14(189.6,74.9) 15(189.6,124.9) 16(189.6,174.9)
  silkscreen extent -213,223 -173,263
DWV0008A [mm] "SOIC, 8-Leads, Body 5.95x7.6mm (max), Pitch 1.27mm"
  rect 1.8x0.6 smd: 1(-5.45,1.905) 2(-5.45,0.635) 3(-5.45,-0.635) 4(-5.45,-1.905) 5(5.45,-1.905) 6(5.45,-0.635) 7(5.45,0.635) 8(5.45,1.905)
  silkscreen extent -4.95,-2.95 2.98,2.95, body extent -3.8,-2.98 3.8,2.98, height 2.81
Fiducial10-30 [mm]
  round 1 smd mask+1: 1(0,0)
  Top Layer keep-out circle w1.678: c0,0 r0.75
IEC_HighVoltage_Large [mil]
  silkscreen extent -435,-352 435,401
Keystone5000 [mil] "For Keystone 500x miniature loop terminals"
  round 80 hole 40: 1(0,0)
  silkscreen extent -58,-58 58,58, body extent -49,-49 49,49, height 182
Label_650x200 [mil] "Thermal Transfer Label"
  round 1 on Mech13: 0(0,0)
  silkscreen extent -325,-100 325,100, body extent -326,-101 326,101, height 1
"LG L29K_GREEN" [mm] "OSRAM"
  rect 0.8x0.8 smd paste-0.4: 1(-0.75,0) 2(0.75,0)
  silkscreen extent -0.1,-0.5 1.45,0.5, body extent -0.9,-0.45 0.9,0.45, height 0.67
MF05A_N [mm] "SOT23, 5-Leads, Body 2.9x1.6mm, Pitch 0.95mm, Lead Span 2.8mm, IPC Medium Density"
  rect 1.1x0.65 smd: 1(-1.2,0.95) 2(-1.2,0) 3(-1.2,-0.95) 4(1.2,-0.95) 5(1.2,0.95)
  silkscreen extent -1.33,-1.55 0.25,1.95, body extent -0.9,-1.55 0.9,1.55, height 1.19
"NY PMS 440 0025 PH" [mm] "4-40 nylon screw and mounting hole"
  round 8 hole 3.2: 1(0,0)
  body extent -3.3,-3.3 3.3,3.3, height 2.69
Pomona_3267 [mm] "Standard Uninsulated Banana Jack"
  round 12 hole 6.858: 1(0,0)
  body extent -4.12,-4.82 4.26,4.85, height 2.79
RELAY_G2RL-2_24 [mm] "OMRON"
  round 1.8 hole 1.3: 1(-11.75,-3.75) 2(3.25,-3.75) 3(8.25,-3.75) 4(13.25,-3.75) 5(13.25,3.75) 6(8.25,3.75) 7(3.25,3.75) 8(-11.75,3.75)
  silkscreen extent -14.05,-6.35 14.95,6.35, body extent -14.05,-6.36 14.95,6.36, height 15.7
SMB [mil] "Molded Diode, 2-Leads, Body 5.4x3.6mm, IPC Medium Density, based on OnSemi component dimensions"
  rect 85x107.99 smd: 1(-87.01,0) 2(87.01,0)
  silkscreen extent -155,-82 125,82, body extent -106,-71 106,71, height 91
sod-323 [mm] "NXP recommended land pattern"
  rect 0.6x0.6 smd paste-0.05: 1(-1.1,0) 2(1.1,0)
  silkscreen extent -2.06,-0.86 1.53,0.86, body extent -1.3,-0.67 1.3,0.68, height 1.1
SON_2X2MM [mm]
  rect 0.4x0.7 smd mask+0.05: 1(-0.65,-1.1) 2(0,-1.1) 3(0.65,-1.1) 4(0.65,1.1) 5(0,1.1) 6(-0.65,1.1)
  rect 1.05x1.2 smd mask+0.05: 7(-0.325,0)
  rect 0.4x0.8 smd mask+0.05: 8(0.65,0.15)
  silkscreen extent -2.33,-1.47 -1.32,-0.46
SOT-89-3 [mm] "SOT, 3-Leads, Body 4.6 x 2.6 mm, Pitch 1.5mm"
  rect 1.4x0.9 smd: 1(-1.9,1.5) 3(-1.9,-1.5)
  rect 1.8x0.9 smd: 2(-1.7,0)
  oct 3.4x1.9 smd: 4(0.9,0)
  silkscreen extent -1.3,-2.45 1.33,2.45, body extent -2.42,-2.28 1.83,2.32, height 1.62
SW_78B04ST [mil] "Switch, DIP Slide, 4Pos"
  rect 60x60 hole 31: 1(-150,150)
  round 60 hole 31: 2(-150,50) 3(-150,-50) 4(-150,-150) 5(150,-150) 6(150,-50) 7(150,50) 8(150,150)
  silkscreen extent -174,213 -160,227, body extent -195,-245 195,245, height 337
TEC_282834-2 [mm] "TEC"
  rect 1.6x1.6 hole 1.1: 1(-1.27,0)
  round 1.6 hole 1.1: 2(1.27,0)
  silkscreen extent -3.66,-3.4 2.9,3.4, body extent -2.77,-3.25 2.77,3.25, height 10.01
TI_Stacked_Overlay_Small [mil]
  silkscreen extent -418,-98 418,98
TP-032_RND [mil]
  round 62 hole 32: 1(0,0)
WURTH_750342773 [mm] "TRANSFORMER, 80 uH, 10%, THRU"
  rect 1.7x1.7 / inner round 1.7 / far side rect 1.7x1.7 hole 1.2 paste+0: 1(-8.395,5.93)
  round 1.7 hole 1.2 paste+0: 2(-8.395,3.23) 3(-8.395,0.53) 4(-8.395,-2.98) 5(-8.395,-5.68) 6(2.145,-6.3) 12(8.395,-4.01) 13(8.395,-1.75) 14(8.395,1.75) 15(8.395,4.01)
  round 1.7 hole 1.2: 7(2.145,6.3) 8(5.395,6.3) 9(5.395,4.01) 10(5.395,-4.01) 11(5.395,-6.3)
  silkscreen extent -12.12,-7.85 11.05,7.85, body extent -11.05,-7.85 11.05,7.85, height 23.3

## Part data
5V_VCC1 5V_VCC2 6V_VCC1 6V_VCC2 V(PRI): "Test Point, Miniature, Red, TH"
C1 C4 C6 C7: "CAP, CERM, 1uF, 10V, +/-10%, X5R, 0805"
C2: "CAP, CERM, 100pF, 50V, +/-5%, C0G/NP0, 0805"
C3 C5 C8 C30 C31: "CAP, CERM, 1000 pF, 25 V, +/- 10%, X7R, 0805"
C9 C10 C12 C13 C14 C18 C19 C25 C26 C36 C37 C38 C39 C40 C41 C44: "CAP, CERM, 0.1 µF, 16 V, +/- 10%, X7R, 0805"
C11 C15 C22 C24 C35 C42 C43: "CAP, CERM, 0.01 µF, 25 V, +/- 5%, C0G/NP0, 0805"
C16 C20 C23 C27: "CAP, CERM, 1uF, 10V, +/-10%, X7R, 0805"
C17 C21: "CAP, CERM, 10 µF, 10 V, +/- 10%, X5R, 1210"
C28: "CAP, CERM, 10 µF, 35 V, +/- 10%, X5R, 1206_190"
C29: "CAP, CERM, 0.1uF, 25V, +/-10%, X7R, 0805"
C32 C33: "CAP, CERM, 22uF, 35V, +/-20%, JB, 0805"
C34: "CAP, CERM, 1uF, 35V, +/-10%, X7R, 0805"
D1: "Diode, Schottky, 5 V, 0.03 A, SOD-323"
D2 D3 D4: "Diode, Schottky, 40V, 1A, SMB"
D5 D9 D10: "Diode, TVS, Uni, 5 V, 600 W, SMB"
D6 D7 D8: "LED, Green, SMD"
"DANGER HIGH VOLTAGE": library part IEC_HighVoltage, "IEC 61010-1 High Voltage Warning"
FID1 FID2 FID3 FID4 FID5 FID6: "Fiducial mark.  There is nothing to buy or mount."
H1 H2 H3 H4: "Machine Screw, Round, #4-40 x 1/4, Nylon, Philips panhead"
J1 J2 J3 J4: "Standard Banana Jack, Uninsulated"
J5 J6 J7 J8: "Terminal Block, 2x1, 2.54mm, TH"
JD1 JD2 JD3 JD4: "Connector, Receptacle, 100mil, 2x1, Gold plated, TH"
K1: "Relay, DPDT, 8A, 5VDC, TH"
LBL1: library part THT-14-423-10, "Thermal Transfer Printable Labels, 0.650\" W x 0.200\" H - 10,000 per roll"
Logo1: library part TI_Logo, "Texas Instrument Corporate Signature"
Q1 Q2: "Trans, Nch, 12V, 20A, 10 mOhm"
Q3: library part "2DD1664R-13, Diodes Inc.", "Transistor, NPN, 32 V, 1 A, SOT-89"
R1 R53 R54: "RES, 1.00 k, 1%, 0.125 W, 0805"
R2 R59 R61 R62: "RES, 499 k, 1%, 0.75 W, 2010"
R3 R43 R44 R58 R60 R63: "RES, 7.50 M, 1%, 0.25 W, 1206"
R4 R9 R18 R20 R22 R24 R25 R29: "RES, 10.0, 0.1%, 0.125 W, 0805"
R5 R7 R21 R23 R26 R28: "RES, 470 ohm, 1%, 0.125W, 0805"
R6: "RES, 6.8k ohm, 5%, 0.25W, 1206"
R8: "RES, 0, 5%, 0.75 W, 2010"
R10: "RES, 51 k, 5%, 0.125 W, 0805"
R11: "RES, 261, 1%, 0.25 W, 1206"
R12: "RES, 2.70 k, 1%, 0.25 W, 1206"
R13: "RES, 220 k, 1%, 0.25 W, 1206"
R14 R15: "RES, 2.00 k, 1%, 0.125 W, 0805"
R16 R17: "RES, 10.0 k, 1%, 0.125 W, 0805"
R19 R64 R65: "RES, 3.0 M, 5%, 0.25 W, 1206"
R27: "RES, 3.0 k, 5%, 0.25 W, 1206"
R30 R31 R32 R33 R34 R36 R37 R38 R39 R40 R41 R42 R47: "RES, 0 ohm, 5%, 0.125W, 0805"
R35: "RES, 10Meg ohm, 5%, 0.25W, 1206"
R45 R57: "RES, 0, 5%, 0.25 W, 1206"
R46: "RES, 126k ohm, 0.1%, 0.125W, 0805"
R48: "RES, 35.2 k, 0.1%, 0.125 W, 0805"
R49: "RES, 145 k, 0.1%, 0.125 W, 0805"
R50: "RES, 12.7 k, 1%, 0.125 W, 0805"
R51: "RES, 19.6 k, 1%, 0.125 W, 0805"
R52: "RES, 20.0 k, 1%, 0.125 W, 0805"
R55 R56: "RES, 0, 5%, 0.125 W, 0805"
S1: "DIP Switch, SPST 4Pos, Slide, TH"
SW: "Test Point, O.032 Hole"
T1: "Transformer, 60 uH, TH"
U1: "Micro-Power (50mA), Zerø-Drift, Rail-to-Rail Out Instrumentation Amplifier"
U2 U4 U5: "Fully-Differential Isolation Amplifier, DWV0008A"
U3: "36-V, Programmable-Gain, Voltage-Output, Bidirectional, Zero-Drift Series, Current-Shunt Monitor, DGK0008A"
U6: "Wide Input 65V, 1.5A Synchronous Step-Down DC-DC Converter, DNT0012B"
U7: "LDO with 6.4 to 15 V Input and 5 V Output, -40 to 125 degC, 8-Pin SON (DRJ), Green (RoHS & no Sb/Br)"
U8: "Micropower 150 mA Low-Noise Ultra Low-Dropout Regulator, 5-pin SOT-23"
U10: "IC, Dual 10 Ohms SPDT Analog Switch"
U11: "IC,Low Power Triple and Quad Channels Digital Isolators"
ZZ1: library part AssemblyNoteLabel
ZZ2 ZZ3 ZZ4: library part AssemblyNote

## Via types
v1: diameter 26, hole 12, Top Layer to Bottom Layer, 122 vias
v2: diameter 19.68, hole 7.87, Top Layer to Bottom Layer, 10 vias

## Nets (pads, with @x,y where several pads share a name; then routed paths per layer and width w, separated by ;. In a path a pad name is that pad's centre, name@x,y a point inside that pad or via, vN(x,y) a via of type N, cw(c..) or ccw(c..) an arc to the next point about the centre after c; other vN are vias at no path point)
3V3: C10.1 C14.1 C24.1 C32.1 C33.1 C37.1 C40.1 R1.1 R50.2 S1.5 S1.6 S1.7 S1.8 T1.4 U2.8 U4.8 U5.8 U11.1 V(PRI).1 | length 788.8
  Top Layer w15: U5.8@3969.57,3166 C37.1@3969.57,3269.57 ; C40.1@3970,1000 3970.57,999.43 U4.8@3970.57,900 ; C14.1@3970,2870 3969.57,2869.57 U2.8@3969.57,2770 v1(4028,2770)
  Top Layer w25: v1(3630,4039) R1.1@3685,4039 ; U11.1@3940.4,214.63 3997.36,214.63 4022,190 C10.1@4081,190 v1(4136,190) ; C37.1@3969.57,3269.57 C37.1@3970,3270 v1(3970,3325) ; C40.1@3970,1000 v1(3970,1055) ; C14.1@3970,2870 v1(3970,2925)
5V_VCC1: 5V_VCC1.1 C9.1 C19.1 C20.1 C38.1 C39.1 C41.1 C44.1 D1.1 K1.1 R30.1 R31.1 R41.1 R53.1 U3.3 U4.1 U7.5 U7.6 U7.7 U7.9 U10.8 U11.16 | length 1464.9
  Top Layer w10: U3.3@2523.36,960.8 2570.8,960.8 2585,975 C39.1@2635,975 ; U10.8@2962,836.6 3001.6,836.6 3035,870 C41.1@3075,870
  Top Layer w15: C9.1@3401,200 3461,200 3475.64,214.63 U11.16@3561.4,214.63 ; v1(3484,900) U4.1@3541.43,900
  Top Layer w25: R53.1@1050,4145 v1(1050,4200) ; C20.1@1140,4140 v1(1140,4200) ; C19.1@1230,4145 v1(1230,4200) ; v1(2130.69,842) R30.1@2130.69,898 ; K1.1@2483.4,1622.36 2485,1620.76 C44.1@2485,1435 ; R31.1@2528.68,1097 v1(2587,1097) ; C39.1@2635,985 v1(2695,985) ; C41.1@3075,870 v1(3135,870) ; v1(3291,514) R41.1@3340,514 ; v1(3336,200) C9.1@3401,200
  Bottom Layer w25: K1.1@2483.4,1622.36 2587.73,1726.69 D1.1@2660,1726.69 ; v1(3484,900) 3505,900 C38.1@3540,865
  other v2: 1415,4085.79 1381.54,4135 1415,4135 1448.46,4135 1415,4184.21
5V_VCC2: 5V_VCC2.1 C12.1 C13.1 C26.1 C27.2 C36.1 R54.1 U1.7 U2.1 U5.1 U8.5 | length 514.6
  Top Layer w12: U1.7@3003.68,2717.48 3048.48,2717.48 3066,2735 3066,2759 3045,2780 C12.1@3045,2833 ; C13.1@3540,2860 3540.43,2859.57 U2.1@3540.43,2770
  Top Layer w15: v1(3480,3168) U5.1@3542.43,3168
  Top Layer w25: C12.1@3045,2833 v1(3045,2890) ; C13.1@3540,2860 v1(3540,2915)
  Bottom Layer w12: v1(3480,3168) 3507,3168 C36.1@3540,3135
  other v1: 929,3674 1039,3674 1085,3675 1135,3675
500V+: JD3.1 JD3.2 R2.1 R61.1 R64.2 | length 3779.6
  Top Layer w25: R61.1@1319.45,2195 R2.1@1319.45,2415 767.66,2415 JD3.1@257.76,2924.9 JD3.2@257.76,3024.9 537.85,3305 2172.91,3305 R64.2@2282.91,3195
500V-: JD4.1 JD4.2 R8.1 R57.1 | length 1032.9
  Top Layer w25: JD4.2@1805,3024.9 JD4.1@1805,2924.9 1979.91,2924.9 2015.55,2960.55 R8.1@2225,2960.55 2489.45,2960.55 2490,2960 R57.1@2722.91,2960
500V_SENSE(+): C8.1 J6.1 R26.2 | length 432.3
  Top Layer w15: R26.2@4225,3141 4270,3141 4280,3131 C8.1@4330,3131 4339,3131 4368,3102 4586,3102 J6.1@4625,3141
500V_SENSE(-): C8.2 J6.2 R28.2 | length 427.3
  Top Layer w15: R28.2@4225,3041 4260,3041 4270,3051 C8.2@4330,3051 4340,3051 4363,3074 4592,3074 J6.2@4625,3041
CSM(+): C5.1 J8.1 R21.2 | length 435.1
  Top Layer w15: R21.2@4221,875 4321,875 C5.1@4326,870 4335,870 4365,840 4585,840 J8.1@4625,880
CSM(-): C5.2 J8.2 R23.2 | length 433
  Top Layer w15: R23.2@4221,780 4316,780 C5.2@4326,790 4338,790 4363,815 4590,815 J8.2@4625,780
GND: C10.2 C11.2 C14.2 C28.2 C29.2 C32.2 C33.2 C34.2 C37.2 C40.2 D6.2 J5.1 R37.2 R38.2 R39.2 R40.2 R51.1 R52.1 U2.5 U4.5 U5.5 U6.1 U6.2 U6.13 U11.2 U11.8 | length 1473.9
  Top Layer w10: v2(3930,3680) U6.13@3959.53,3650.47 ; U6.1@4004.8,3630.79 3979.21,3630.79 U6.13@3959.53,3650.47 ; U6.2@4004.8,3650.47 U6.13@3959.53,3650.47
  Top Layer w15: U2.5@3955.57,2620 v1(4027,2620) ; U5.5@3969.57,3016 v1(4032,3016) ; U4.5@3970.57,750 v1(4029,750)
  Top Layer w25: C33.2@3436,4061 v1(3436,4115) ; v1(3437,3760) C32.2@3437,3820 ; v1(3643,4128) D6.2@3694.47,4128 ; R52.1@3720,3900 v1(3720,3950) ; C34.2@3885,3850 v1(3885,3905) ; U11.2@3940.4,264.64 4010.36,264.64 4015.73,270 C10.2@4081,270 v1(4136,270) ; U11.8@3940.4,564.64 4014.64,564.64 v1(4015,565) ; C11.2@3960,3850 v1(3960,3905) ; C40.2@4050,1000 v1(4050,1055) ; C14.2@4050,2870 v1(4050,2925) ; C37.2@4050,3270 v1(4050,3325) ; v1(4115,3510) C29.2@4115,3565 ; R51.1@4120,3880 v1(4120,3945) ; v1(4219,3463) C28.2@4219,3511.07 ; R40.2@4309,259 v1(4360,259) ; R38.2@4310,474 v1(4363,474) ; R39.2@4311,364 v1(4365,364) ; R37.2@4311,582 v1(4363,582)
  other v1: 3375,4070 3500,4070 3500,4110 3375,4115
  other v2: 3930,3632.76 3890.63,3680 3969.37,3680 3930,3727.24
GND1: C9.2 C16.2 C17.2 C18.2 C19.2 C20.2 C38.2 C39.2 C41.2 C42.1 C43.2 C44.2 D7.2 Q3.3 R33.1 R34.1 R42.1 R55.1 T1.12 U3.2 U3.7 U4.4 U7.1 U10.3 U10.4 U11.9 U11.15 | length 1873.6
  Top Layer w10: v1@1489.8,4020 U7.1@1489.8,4087.76 ; U3.2@2523.36,935.2 2569.8,935.2 2600,905 C39.2@2635,905 ; v1@2730.5,848.5 2742.4,836.6 U10.3@2796,836.6 ; v1(2739,808) 2747.9,816.9 U10.4@2796,816.9
  Top Layer w15: v1(2287,921) 2301.2,935.2 U3.7@2358.01,935.2 ; C9.2@3401,280 3466,280 3481.36,264.64 U11.15@3561.4,264.64 ; v1(3482,750) U4.4@3541.43,750
  Top Layer w25: D7.2@1109.53,3965 v1(1159,3965) ; v1(1140,4015) C20.2@1140,4065 ; v1(1230,4015) C19.2@1230,4065 ; v1(1600,4020) C18.2@1600,4070 ; v1(1695,4020) C16.2@1695,4070 ; v1(1775,4020) 1775,4067.91 C17.2@1815,4067.91 ; v1(1815,4020) C17.2@1815,4067.91 ; v1(1855,4020) 1855,4065 1852.09,4067.91 C17.2@1815,4067.91 ; R33.1@2130.69,988 v1(2130.69,1046.69) v1@2131,1047 ; v1(2218,1097) R34.1@2278.69,1097 ; R55.1@2220,599 v1(2220,652) ; v1(2242,716) C43.2@2242,773 ; Q3.3@2326.8,1892.06 v1(2326.8,1953.2) ; C44.2@2565,1435 v1(2625,1435) ; C39.2@2635,905 v1(2695,905) ; C42.1@2649,774 v1(2696,774) ; C41.2@3075,790 v1(3135,790) ; v1(3291,604) R42.1@3340,604 ; v1(3336,280) C9.2@3401,280 ; v1(3490,565) 3490.36,564.64 U11.9@3561.4,564.64
  Bottom Layer w25: v1(3482,750) 3505,750 C38.2@3540,785
  other v1: 2730,848 1490,4020 1555,4020 1645,4020 1900,4020 1900,4060 1530,4070
GND2: C2.2 C12.2 C13.2 C15.1 C21.1 C23.2 C25.2 C26.2 C27.1 C30.2 C35.1 C35.2 C36.2 D8.2 D9.2 K1.6 R6.1 R8.2 R9.1 R43.1 R56.1 T1.8 U1.2 U1.4 U1.5 U2.4 U5.4 U8.2 | length 1914.6
  Top Layer w10: 2773,2718 2773.52,2717.48 ; v1(2838,2636) v1@2838.32,2636.32
  Top Layer w12: U1.5@3003.68,2666.3 3049.7,2666.3 v1(3066,2650)
  Top Layer w15: v1(2634,2714) 2662,2742 C2.2@2704,2742 2749,2742 2773,2718 ; 2773.52,2717.48 U1.2@2838.32,2717.48 ; v1@2838.32,2636.32 U1.4@2838.32,2666.3 ; v1(3480,3017) U5.4@3539.43,3017 ; U2.4@3540.43,2620 3552.13,2620 3552.13,2587.87 v1(3561.06,2578.94)
  Top Layer w25: v1(828.69,3453.94) 829.69,3454.94 D8.2@829.69,3509.41 ; v1(1019,3489) C27.1@1019,3539 ; v1(1109,3489) C26.2@1109,3539 ; U8.2@1332.93,3672 1389,3672 1407,3690 v1(1410,3690) ; v1(1569,3500) C25.2@1569,3550 ; v1(1664,3500) C23.2@1664,3550 ; v1(1739,3465) 1739,3515 1741.91,3517.91 C21.1@1779,3517.91 ; v1(1779,3465) C21.1@1779,3517.91 ; v1(1819,3465) 1819,3510 1811.09,3517.91 C21.1@1779,3517.91 ; v1@2120,2780 v1(2120.55,2779.45) R8.2@2225,2779.45 ; R6.1@2424,2821.09 v1(2424,2873) ; R43.1@2535.09,2415 2593,2415 v1(2625,2447) ; D9.2@2569,2801.01 v1(2569,2870) ; C15.1@2704,2496 v1(2767,2496) ; C2.2@2704,2742 C35.1@2704,2832 ; v1(2784,2773) C35.2@2784,2832 ; C12.2@3125,2833 v1(3125,2885) ; v1(3151,2695) R9.1@3206,2695 ; R56.1@3315,2961 v1(3365,2961) ; C13.2@3460,2860 v1(3460,2915)
  Bottom Layer w25: 1312,3735 1312,3668 C30.2@1315,3665 ; v1(3480,3017) 3502,3017 C36.2@3540,3055
  other v1: 1860,3465 1900,3465 1525,3500 1615,3500 1860,3505 1322,3745
ISENSE: D10.1 R11.2 R12.2 R13.2 R20.1 R45.1 U10.9 | length 2219.7
  Top Layer w10: R13.2@2713.91,584 2713.91,693.91 2740,720 2820,720 2881,781 2881,827 2910.3,856.3 U10.9@2962,856.3
  Top Layer w15: R45.1@2155,1442.91 2142.91,1442.91 2035,1335 2035,210 2090,155 2490,155
MID: D10.2 K1.3 Q1.4 Q1.8 Q2.4 Q2.8 R13.1 R16.1 R17.1 R24.1 R55.2 U10.7 | length 3966.1
  Top Layer w10: 2910,589 2910,810 2916.9,816.9 U10.7@2962,816.9
  Top Layer w15: 2200,425 2100,425 2070,455 2070,1225 2190,1345 2993.44,1345 K1.3@3270.8,1622.36 ; v1(2315,360) 2315.99,360.99 D10.2@2315.99,469 ; R13.1@2828.09,584 v1@2828.09,644.91 ; Q2.4@2994.9,505 R17.1@3099,505 ; v1(3003.11,342) 3003.39,341.72 Q1.4@3003.39,298.31 Q1.8@3003.39,260.91 ; Q1.4@3006.7,295 R16.1@3097.11,295
  Bottom Layer w15: v1(2315,360) 2745,360 2828,443 ; v1(2828,645) 2828,443 ; v1(3003.11,342) 2929,342 2828,443
MUX: U10.1 U10.5 U11.11 | length 1208.9
  Top Layer w10: v1(2735,750) 2780,750 2796,766 U10.5@2796,797.2 2835.2,797.2 2845,807 2845,864 2833,876 U10.1@2796,876
  Top Layer w15: v1@3496,464 v1(3497,465) 3497.36,464.64 U11.11@3561.4,464.64
  Bottom Layer w15: v1(2735,750) 2895,750 3000,645 3317,645 v1(3497,465)
Net6V_VCC1_1: 6V_VCC1.1 C16.1 C17.1 C18.1 D2.1 U7.2 U7.3 U7.4
Net6V_VCC2_1: 6V_VCC2.1 C21.2 C23.1 C25.1 D3.1 R47.2 U8.1
NetC1_1: C1.1 R4.2 U2.2 | length 279.3
  Top Layer w15: R4.2@3286,2780 3291,2775 C1.1@3376,2775 3420,2775 3475,2720 U2.2@3540.43,2720
NetC1_2: C1.2 R9.2 U2.3 | length 264.8
  Top Layer w15: R9.2@3286,2695 C1.2@3376,2695 3445,2695 3470,2670 U2.3@3540.43,2670
NetC2_1: C2.1 C15.2 D9.1 R3.1 R6.2 U1.3 | length 607.1
  Top Layer w15: R6.2@2424,2706.91 R3.1@2424,2627.09 2424.09,2626.99 D9.1@2569,2626.99 2596.01,2654 2687,2654 2695,2662 C2.1@2704,2662 ; C15.2@2704,2576 C2.1@2704,2662 ; U1.3@2838.32,2691.89 2775.89,2691.89 2746,2662 C2.1@2704,2662
NetC4_1: C4.1 R18.2 U4.2 | length 273.7
  Top Layer w15: R18.2@3276,870 3281,865 C4.1@3376,865 3447,865 3462,850 U4.2@3541.43,850
NetC4_2: C4.2 R25.2 U4.3 | length 273.7
  Top Layer w15: R25.2@3276,780 3281,785 C4.2@3376,785 3450,785 3465,800 U4.3@3541.43,800
NetC6_1: C6.1 C42.2 R20.2 U3.1 | length 326.8
  Top Layer w15: R20.2@2494,685 2494,723 2486,731 C6.1@2486,773 ; U3.1@2523.36,909.61 2523.36,883.36 2486,846 C6.1@2486,773 ; C42.2@2569,774 2487,774 C6.1@2486,773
